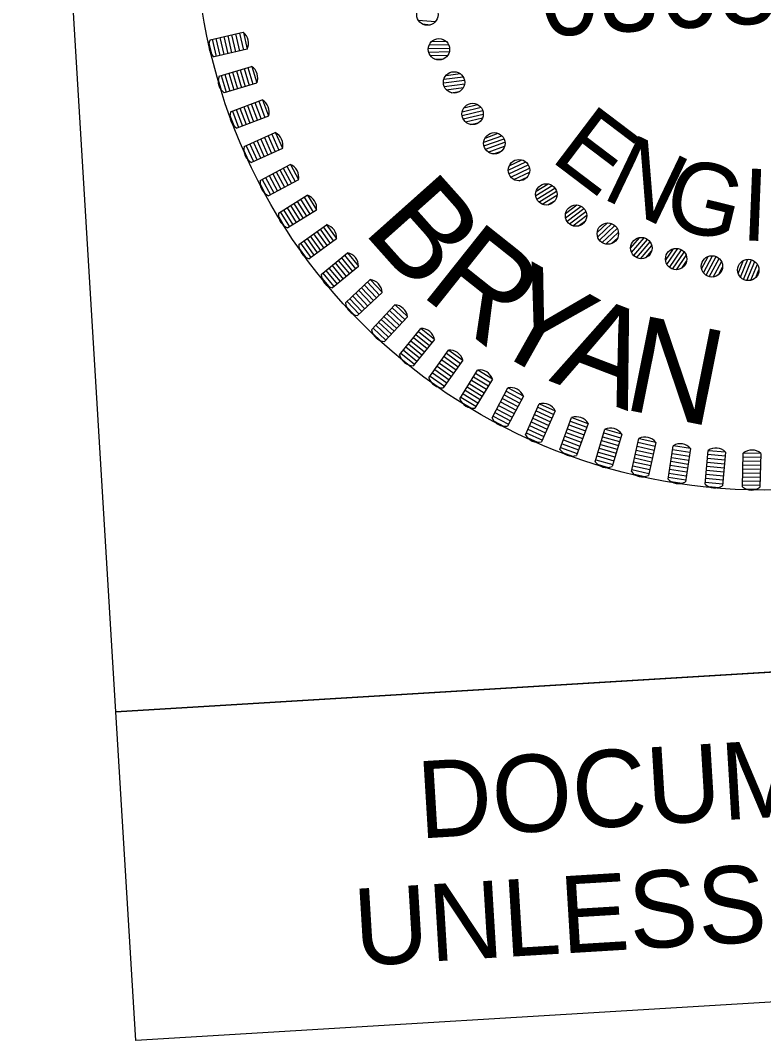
# Model space of a CAD drawing. Extents: x 2110128 to 2112690, y 669500 to 671339.
# Drawn here: x 2112240.6 to 2112293.6, y 670625.1 to 670697.9 of the extents above; entities that cross this region are included whole.
import ezdxf

# ---------------------------------------------------------------- set-up
doc = ezdxf.new("R2010")
doc.units = 0
for name, color, linetype in [('Exist Roads Curbs Text', 7, 'Continuous'), ('Exist Utilities Power Transformer Cogo Comment', 7, 'Continuous'), ('Exist Vegetation Woods Line Text', 7, 'Continuous')]:
    doc.layers.add(name, color=color, linetype=linetype)

msp = doc.modelspace()

# ---------------------------------------------------------------- linework, layer by layer
at = {"layer": 'Exist Roads Curbs Text'}
msp.add_lwpolyline([(2112240.598, 670760.885), (2112340.465, 670766.938), (2112347.271, 670654.644), (2112247.404, 670648.591)], close=True, dxfattribs=at)
at = {"layer": 'Exist Utilities Power Transformer Cogo Comment'}
for p, q in [((2112247.404, 670648.591), (2112447.075, 670660.693)), ((2112248.826, 670625.134), (2112247.404, 670648.591)), ((2112448.497, 670637.236), (2112248.826, 670625.134))]:
    msp.add_line(p, q, dxfattribs=at)
at = {"layer": 'Exist Vegetation Woods Line Text'}
for p, q in [((2112268.955, 670697.909), (2112270.191, 670697.812)), ((2112269.246, 670697.632), (2112269.86, 670697.583)), ((2112254.119, 670696.505), (2112256.474, 670697.047)), ((2112254.262, 670696.538), (2112254.543, 670695.32)), ((2112254.54, 670696.602), (2112254.821, 670695.384)), ((2112254.818, 670696.666), (2112255.099, 670695.448)), ((2112255.096, 670696.73), (2112255.377, 670695.512)), ((2112255.374, 670696.794), (2112255.655, 670695.576)), ((2112255.652, 670696.858), (2112255.933, 670695.64)), ((2112255.93, 670696.922), (2112256.211, 670695.704)), ((2112256.208, 670696.986), (2112256.489, 670695.768)), ((2112256.49, 670697.035), (2112256.763, 670695.847)), ((2112269.916, 670696.393), (2112270.921, 670696.419)), ((2112254.039, 670696.236), (2112254.21, 670695.494)), ((2112256.754, 670695.829), (2112254.399, 670695.287)), ((2112269.673, 670695.879), (2112271.191, 670695.918)), ((2112269.7, 670695.625), (2112271.176, 670695.663)), ((2112269.733, 670696.134), (2112271.117, 670696.17)), ((2112269.825, 670695.374), (2112271.065, 670695.406)), ((2112270.144, 670695.128), (2112270.759, 670695.144)), ((2112254.763, 670693.916), (2112257.077, 670694.612)), ((2112255.723, 670694.205), (2112256.083, 670693.008)), ((2112255.996, 670694.287), (2112256.357, 670693.09)), ((2112256.27, 670694.369), (2112256.63, 670693.172)), ((2112256.543, 670694.452), (2112256.903, 670693.254)), ((2112256.816, 670694.534), (2112257.176, 670693.337)), ((2112257.094, 670694.601), (2112257.445, 670693.434)), ((2112254.701, 670693.642), (2112254.92, 670692.913)), ((2112254.904, 670693.958), (2112255.264, 670692.761)), ((2112255.177, 670694.041), (2112255.537, 670692.844)), ((2112255.45, 670694.123), (2112255.81, 670692.926)), ((2112270.751, 670693.43), (2112272.257, 670693.627)), ((2112270.784, 670693.69), (2112272.157, 670693.871)), ((2112270.939, 670693.967), (2112271.936, 670694.098)), ((2112257.437, 670693.415), (2112255.123, 670692.719)), ((2112270.805, 670693.181), (2112272.269, 670693.373)), ((2112270.955, 670692.944), (2112272.185, 670693.106)), ((2112271.298, 670692.733), (2112271.908, 670692.813)), ((2112255.576, 670691.375), (2112257.84, 670692.223)), ((2112257.317, 670692.027), (2112257.756, 670690.856)), ((2112257.584, 670692.127), (2112258.023, 670690.956)), ((2112257.857, 670692.213), (2112258.284, 670691.071)), ((2112255.714, 670691.427), (2112256.153, 670690.256)), ((2112255.981, 670691.527), (2112256.42, 670690.356)), ((2112256.248, 670691.627), (2112256.687, 670690.456)), ((2112256.516, 670691.727), (2112256.954, 670690.556)), ((2112256.783, 670691.827), (2112257.221, 670690.656)), ((2112257.05, 670691.927), (2112257.488, 670690.756)), ((2112272.079, 670691.107), (2112273.556, 670691.461)), ((2112272.085, 670691.37), (2112273.432, 670691.692)), ((2112272.21, 670691.661), (2112273.188, 670691.895)), ((2112255.533, 670691.098), (2112255.8, 670690.385)), ((2112258.278, 670691.052), (2112256.015, 670690.204)), ((2112272.159, 670690.865), (2112273.595, 670691.209)), ((2112272.333, 670690.645), (2112273.539, 670690.934)), ((2112272.696, 670690.471), (2112273.294, 670690.614)), ((2112256.556, 670688.893), (2112258.758, 670689.889)), ((2112258.776, 670689.88), (2112259.278, 670688.769)), ((2112273.716, 670689.5), (2112274.663, 670689.836)), ((2112257.21, 670689.189), (2112257.725, 670688.05)), ((2112257.47, 670689.306), (2112257.985, 670688.167)), ((2112257.73, 670689.424), (2112258.245, 670688.285)), ((2112257.99, 670689.541), (2112258.505, 670688.402)), ((2112258.25, 670689.659), (2112258.765, 670688.52)), ((2112258.51, 670689.776), (2112259.025, 670688.637)), ((2112273.622, 670689.198), (2112274.927, 670689.659)), ((2112273.643, 670688.936), (2112275.075, 670689.442)), ((2112273.748, 670688.703), (2112275.14, 670689.196)), ((2112256.531, 670688.614), (2112256.845, 670687.92)), ((2112256.69, 670688.954), (2112257.205, 670687.815)), ((2112256.95, 670689.071), (2112257.465, 670687.932)), ((2112259.273, 670688.749), (2112257.071, 670687.754)), ((2112273.944, 670688.503), (2112275.113, 670688.917)), ((2112274.323, 670688.368), (2112274.903, 670688.573)), ((2112275.377, 670687.198), (2112276.626, 670687.794)), ((2112275.438, 670687.509), (2112276.346, 670687.941)), ((2112257.698, 670686.482), (2112259.829, 670687.62)), ((2112258.582, 670686.954), (2112259.171, 670685.852)), ((2112258.834, 670687.089), (2112259.423, 670685.986)), ((2112259.086, 670687.223), (2112259.675, 670686.12)), ((2112259.337, 670687.357), (2112259.926, 670686.255)), ((2112259.589, 670687.492), (2112260.178, 670686.389)), ((2112259.848, 670687.613), (2112260.422, 670686.537)), ((2112275.425, 670686.94), (2112276.796, 670687.593)), ((2112275.554, 670686.719), (2112276.887, 670687.355)), ((2112275.77, 670686.541), (2112276.889, 670687.074)), ((2112257.691, 670686.201), (2112258.05, 670685.529)), ((2112257.828, 670686.551), (2112258.417, 670685.448)), ((2112258.079, 670686.685), (2112258.668, 670685.583)), ((2112260.418, 670686.518), (2112258.287, 670685.379)), ((2112258.331, 670686.82), (2112258.92, 670685.717)), ((2112276.161, 670686.446), (2112276.716, 670686.711)), ((2112277.36, 670685.708), (2112278.217, 670686.233)), ((2112277.331, 670685.393), (2112278.512, 670686.116)), ((2112277.406, 670685.141), (2112278.702, 670685.934)), ((2112277.557, 670684.935), (2112278.816, 670685.707)), ((2112258.996, 670684.151), (2112261.048, 670685.428)), ((2112260.09, 670684.831), (2112260.75, 670683.77)), ((2112260.332, 670684.982), (2112260.993, 670683.921)), ((2112260.574, 670685.133), (2112261.235, 670684.072)), ((2112260.816, 670685.284), (2112261.477, 670684.223)), ((2112261.067, 670685.421), (2112261.711, 670684.386)), ((2112277.791, 670684.781), (2112278.848, 670685.428)), ((2112278.19, 670684.727), (2112278.714, 670685.048)), ((2112259.121, 670684.228), (2112259.782, 670683.167)), ((2112259.363, 670684.379), (2112260.024, 670683.318)), ((2112259.605, 670684.53), (2112260.266, 670683.469)), ((2112261.708, 670684.367), (2112259.657, 670683.089)), ((2112259.848, 670684.681), (2112260.508, 670683.619)), ((2112279.459, 670684.119), (2112280.257, 670684.73)), ((2112279.463, 670683.802), (2112280.562, 670684.644)), ((2112279.565, 670683.559), (2112280.77, 670684.484)), ((2112279.736, 670683.371), (2112280.908, 670684.269)), ((2112259.008, 670683.87), (2112259.411, 670683.224)), ((2112260.446, 670681.911), (2112262.409, 670683.321)), ((2112262.428, 670683.315), (2112263.139, 670682.325)), ((2112279.985, 670683.241), (2112280.969, 670683.995)), ((2112280.387, 670683.229), (2112280.875, 670683.604)), ((2112281.713, 670682.757), (2112282.443, 670683.449)), ((2112281.75, 670682.442), (2112282.755, 670683.395)), ((2112261.492, 670682.662), (2112262.221, 670681.647)), ((2112261.724, 670682.829), (2112262.453, 670681.813)), ((2112261.955, 670682.995), (2112262.685, 670681.98)), ((2112262.187, 670683.162), (2112262.916, 670682.146)), ((2112281.877, 670682.212), (2112282.979, 670683.257)), ((2112282.067, 670682.042), (2112283.138, 670683.058)), ((2112282.327, 670681.939), (2112283.227, 670682.792)), ((2112260.565, 670681.997), (2112261.295, 670680.981)), ((2112260.797, 670682.163), (2112261.526, 670681.148)), ((2112261.029, 670682.329), (2112261.758, 670681.314)), ((2112263.138, 670682.305), (2112261.175, 670680.895)), ((2112261.26, 670682.496), (2112261.99, 670681.481)), ((2112282.729, 670681.97), (2112283.175, 670682.393)), ((2112284.097, 670681.639), (2112284.75, 670682.403)), ((2112284.167, 670681.33), (2112285.067, 670682.382)), ((2112284.317, 670681.113), (2112285.303, 670682.268)), ((2112284.523, 670680.964), (2112285.483, 670682.087)), ((2112284.793, 670680.889), (2112285.599, 670681.832)), ((2112260.476, 670681.632), (2112260.921, 670681.013)), ((2112262.04, 670679.771), (2112263.906, 670681.308)), ((2112263.695, 670681.135), (2112264.49, 670680.17)), ((2112263.925, 670681.304), (2112264.7, 670680.363)), ((2112285.189, 670680.962), (2112285.589, 670681.429)), ((2112286.585, 670680.776), (2112287.154, 670681.604)), ((2112286.687, 670680.475), (2112287.471, 670681.616)), ((2112286.858, 670680.276), (2112287.719, 670681.527)), ((2112287.079, 670680.149), (2112287.916, 670681.366)), ((2112287.356, 670680.103), (2112288.058, 670681.125)), ((2112289.282, 670679.889), (2112289.943, 670681.106)), ((2112262.815, 670680.409), (2112263.609, 670679.444)), ((2112263.035, 670680.591), (2112263.83, 670679.626)), ((2112263.255, 670680.772), (2112264.05, 670679.807)), ((2112263.475, 670680.953), (2112264.27, 670679.988)), ((2112287.742, 670680.216), (2112288.091, 670680.723)), ((2112289.149, 670680.177), (2112289.629, 670681.06)), ((2112289.473, 670679.709), (2112290.198, 670681.043)), ((2112289.706, 670679.606), (2112290.411, 670680.904)), ((2112289.986, 670679.589), (2112290.578, 670680.678)), ((2112291.762, 670679.85), (2112292.147, 670680.779)), ((2112291.924, 670679.578), (2112292.454, 670680.857)), ((2112292.133, 670679.418), (2112292.715, 670680.821)), ((2112292.376, 670679.34), (2112292.941, 670680.705)), ((2112292.656, 670679.352), (2112293.131, 670680.498)), ((2112262.154, 670679.865), (2112262.949, 670678.9)), ((2112262.374, 670680.046), (2112263.169, 670679.082)), ((2112262.594, 670680.228), (2112263.389, 670679.263)), ((2112264.701, 670680.343), (2112262.835, 670678.807)), ((2112290.358, 670679.742), (2112290.652, 670680.283)), ((2112293.01, 670679.544), (2112293.246, 670680.112)), ((2112262.089, 670679.495), (2112262.573, 670678.907)), ((2112263.773, 670677.742), (2112265.532, 670679.399)), ((2112265.126, 670679.016), (2112265.983, 670678.106)), ((2112265.334, 670679.212), (2112266.191, 670678.302)), ((2112265.552, 670679.396), (2112266.388, 670678.509)), ((2112264.295, 670678.234), (2112265.152, 670677.324)), ((2112264.503, 670678.43), (2112265.36, 670677.52)), ((2112266.389, 670678.489), (2112264.63, 670676.832)), ((2112264.711, 670678.625), (2112265.568, 670677.715)), ((2112264.919, 670678.821), (2112265.775, 670677.911)), ((2112263.84, 670677.47), (2112264.362, 670676.915)), ((2112263.88, 670677.843), (2112264.737, 670676.933)), ((2112264.088, 670678.039), (2112264.945, 670677.129)), ((2112265.636, 670675.832), (2112267.282, 670677.601)), ((2112267.302, 670677.6), (2112268.194, 670676.769)), ((2112266.513, 670676.775), (2112267.428, 670675.924)), ((2112268.197, 670676.75), (2112266.551, 670674.98)), ((2112266.708, 670676.984), (2112267.623, 670676.132)), ((2112266.902, 670677.193), (2112267.817, 670676.341)), ((2112267.096, 670677.402), (2112268.011, 670676.55)), ((2112265.93, 670676.149), (2112266.845, 670675.297)), ((2112266.125, 670676.357), (2112267.04, 670675.506)), ((2112266.319, 670676.566), (2112267.234, 670675.715)), ((2112265.72, 670675.565), (2112266.278, 670675.046)), ((2112265.736, 670675.94), (2112266.651, 670675.088)), ((2112267.621, 670674.049), (2112269.146, 670675.923)), ((2112268.794, 670675.491), (2112269.764, 670674.701)), ((2112268.974, 670675.712), (2112269.944, 670674.923)), ((2112269.166, 670675.923), (2112270.112, 670675.154)), ((2112268.074, 670674.606), (2112269.043, 670673.816)), ((2112268.254, 670674.827), (2112269.223, 670674.038)), ((2112268.434, 670675.048), (2112269.403, 670674.259)), ((2112270.116, 670675.134), (2112268.59, 670673.26)), ((2112268.614, 670675.269), (2112269.583, 670674.48)), ((2112267.714, 670674.163), (2112268.683, 670673.374)), ((2112267.894, 670674.384), (2112268.863, 670673.595)), ((2112269.719, 670672.401), (2112271.118, 670674.372)), ((2112270.795, 670673.917), (2112271.814, 670673.194)), ((2112270.96, 670674.15), (2112271.979, 670673.426)), ((2112271.138, 670674.373), (2112272.132, 670673.668)), ((2112267.723, 670673.788), (2112268.313, 670673.307)), ((2112270.299, 670673.219), (2112271.319, 670672.496)), ((2112270.465, 670673.452), (2112271.484, 670672.728)), ((2112270.63, 670673.684), (2112271.649, 670672.961)), ((2112272.137, 670673.649), (2112270.739, 670671.678)), ((2112269.804, 670672.521), (2112270.824, 670671.798)), ((2112269.969, 670672.754), (2112270.989, 670672.03)), ((2112270.134, 670672.987), (2112271.154, 670672.263)), ((2112271.922, 670670.896), (2112273.187, 670672.955)), ((2112272.895, 670672.479), (2112273.96, 670671.825)), ((2112273.044, 670672.722), (2112274.109, 670672.068)), ((2112273.207, 670672.957), (2112274.245, 670672.319)), ((2112269.838, 670672.147), (2112270.459, 670671.707)), ((2112272.447, 670671.75), (2112273.512, 670671.096)), ((2112272.596, 670671.993), (2112273.661, 670671.339)), ((2112272.746, 670672.236), (2112273.811, 670671.582)), ((2112274.252, 670672.3), (2112272.987, 670670.241)), ((2112274.219, 670669.539), (2112275.346, 670671.677)), ((2112275.365, 670671.681), (2112276.444, 670671.113)), ((2112271.999, 670671.021), (2112273.064, 670670.367)), ((2112272.148, 670671.264), (2112273.213, 670670.61)), ((2112272.298, 670671.507), (2112273.363, 670670.853)), ((2112274.953, 670670.931), (2112276.059, 670670.348)), ((2112275.086, 670671.183), (2112276.192, 670670.601)), ((2112275.219, 670671.436), (2112276.325, 670670.853)), ((2112276.452, 670671.094), (2112275.325, 670668.956)), ((2112272.058, 670670.65), (2112272.706, 670670.251)), ((2112274.687, 670670.426), (2112275.793, 670669.844)), ((2112274.82, 670670.679), (2112275.926, 670670.096)), ((2112276.601, 670668.337), (2112277.584, 670670.545)), ((2112277.473, 670670.296), (2112278.615, 670669.787)), ((2112277.603, 670670.55), (2112278.717, 670670.054)), ((2112274.288, 670669.669), (2112275.394, 670669.086)), ((2112274.421, 670669.922), (2112275.527, 670669.339)), ((2112274.554, 670670.174), (2112275.66, 670669.591)), ((2112277.125, 670669.514), (2112278.267, 670669.006)), ((2112277.241, 670669.775), (2112278.383, 670669.266)), ((2112277.357, 670670.035), (2112278.499, 670669.527)), ((2112278.726, 670670.037), (2112277.743, 670667.829)), ((2112279.058, 670667.295), (2112279.892, 670669.563)), ((2112279.911, 670669.57), (2112281.055, 670669.149)), ((2112274.371, 670669.303), (2112275.045, 670668.948)), ((2112276.777, 670668.732), (2112277.919, 670668.224)), ((2112276.893, 670668.993), (2112278.035, 670668.484)), ((2112277.009, 670669.253), (2112278.151, 670668.745)), ((2112279.601, 670668.772), (2112280.774, 670668.34)), ((2112279.7, 670669.04), (2112280.873, 670668.608)), ((2112279.798, 670669.307), (2112280.971, 670668.876)), ((2112281.065, 670669.132), (2112280.231, 670666.863)), ((2112281.578, 670666.418), (2112282.26, 670668.736)), ((2112282.279, 670668.744), (2112283.448, 670668.399)), ((2112276.661, 670668.471), (2112277.803, 670667.963)), ((2112276.768, 670668.112), (2112277.464, 670667.802)), ((2112279.404, 670668.236), (2112280.577, 670667.805)), ((2112279.503, 670668.504), (2112280.676, 670668.072)), ((2112282.103, 670668.201), (2112283.302, 670667.848)), ((2112282.183, 670668.475), (2112283.382, 670668.121)), ((2112283.46, 670668.383), (2112282.777, 670666.065)), ((2112284.15, 670665.709), (2112284.678, 670668.067)), ((2112284.696, 670668.076), (2112285.885, 670667.81)), ((2112279.109, 670667.433), (2112280.282, 670667.002)), ((2112279.207, 670667.701), (2112280.38, 670667.269)), ((2112279.306, 670667.969), (2112280.479, 670667.537)), ((2112281.861, 670667.38), (2112283.06, 670667.027)), ((2112281.942, 670667.654), (2112283.141, 670667.3)), ((2112282.022, 670667.927), (2112283.221, 670667.574)), ((2112284.556, 670667.523), (2112285.776, 670667.25)), ((2112284.618, 670667.801), (2112285.838, 670667.528)), ((2112285.898, 670667.794), (2112285.37, 670665.436)), ((2112286.763, 670665.172), (2112287.134, 670667.56)), ((2112287.093, 670667.291), (2112288.328, 670667.099)), ((2112287.152, 670667.57), (2112288.356, 670667.383)), ((2112288.37, 670667.368), (2112287.999, 670664.98)), ((2112279.239, 670667.081), (2112279.954, 670666.818)), ((2112281.619, 670666.559), (2112282.818, 670666.206)), ((2112281.7, 670666.833), (2112282.899, 670666.48)), ((2112281.78, 670667.106), (2112282.979, 670666.753)), ((2112284.369, 670666.688), (2112285.589, 670666.415)), ((2112284.431, 670666.966), (2112285.651, 670666.693)), ((2112284.494, 670667.245), (2112285.714, 670666.971)), ((2112287.005, 670666.727), (2112288.24, 670666.535)), ((2112287.049, 670667.009), (2112288.284, 670666.817)), ((2112289.407, 670664.809), (2112289.619, 670667.216)), ((2112289.57, 670666.66), (2112290.815, 670666.55)), ((2112289.595, 670666.944), (2112290.84, 670666.834)), ((2112289.636, 670667.227), (2112290.85, 670667.12)), ((2112290.864, 670667.106), (2112290.652, 670664.699)), ((2112292.068, 670664.621), (2112292.121, 670667.037)), ((2112292.115, 670666.764), (2112293.365, 670666.737)), ((2112292.137, 670667.049), (2112293.356, 670667.022)), ((2112293.371, 670667.01), (2112293.318, 670664.593)), ((2112281.773, 670666.216), (2112282.503, 670666.001)), ((2112284.182, 670665.853), (2112285.402, 670665.58)), ((2112284.244, 670666.131), (2112285.464, 670665.858)), ((2112284.307, 670666.41), (2112285.527, 670666.136)), ((2112286.874, 670665.881), (2112288.109, 670665.689)), ((2112286.917, 670666.163), (2112288.153, 670665.971)), ((2112286.961, 670666.445), (2112288.196, 670666.253)), ((2112289.52, 670666.092), (2112290.765, 670665.982)), ((2112289.545, 670666.376), (2112290.79, 670666.266)), ((2112292.096, 670665.909), (2112293.346, 670665.881)), ((2112292.103, 670666.194), (2112293.352, 670666.167)), ((2112292.109, 670666.479), (2112293.359, 670666.452)), ((2112284.358, 670665.521), (2112285.101, 670665.355)), ((2112286.786, 670665.317), (2112288.021, 670665.125)), ((2112286.83, 670665.599), (2112288.065, 670665.407)), ((2112289.445, 670665.239), (2112290.69, 670665.13)), ((2112289.47, 670665.524), (2112290.715, 670665.414)), ((2112289.495, 670665.808), (2112290.74, 670665.698)), ((2112292.084, 670665.338), (2112293.334, 670665.311)), ((2112292.09, 670665.624), (2112293.34, 670665.596)), ((2112286.984, 670664.998), (2112287.736, 670664.881)), ((2112289.42, 670664.955), (2112290.665, 670664.845)), ((2112289.638, 670664.65), (2112290.396, 670664.583)), ((2112292.071, 670664.768), (2112293.321, 670664.741)), ((2112292.078, 670665.053), (2112293.327, 670665.026)), ((2112292.309, 670664.477), (2112293.071, 670664.461))]:
    msp.add_line(p, q, dxfattribs=at)
for centre, radius in [((2112293.63, 670704.945), 40.556), ((2112269.608, 670698.302), 0.762), ((2112270.433, 670695.834), 0.762), ((2112271.512, 670693.464), 0.762), ((2112272.833, 670691.221), 0.762), ((2112274.381, 670689.128), 0.762), ((2112276.139, 670687.208), 0.762), ((2112278.088, 670685.482), 0.762), ((2112280.207, 670683.97), 0.762), ((2112282.472, 670682.687), 0.762), ((2112284.859, 670681.649), 0.762), ((2112287.342, 670680.865), 0.762), ((2112289.893, 670680.345), 0.762), ((2112292.484, 670680.095), 0.762)]:
    msp.add_circle(centre, radius, dxfattribs=at)
for centre, radius, start, end in [((2112255.06, 670696.08), 1.032, 155.68573, 230.2267), ((2112255.875, 670696.268), 0.983, 333.45947, 52.45296), ((2112256.531, 670693.795), 0.983, 337.24894, 56.24243), ((2112255.729, 670693.554), 1.032, 159.4752, 234.01617), ((2112257.349, 670691.371), 0.983, 341.03842, 60.03191), ((2112256.565, 670691.078), 1.032, 163.26468, 237.80565), ((2112258.325, 670689.007), 0.983, 344.82789, 63.82138), ((2112257.562, 670688.662), 1.032, 167.05415, 241.59512), ((2112259.455, 670686.712), 0.983, 348.61736, 67.61086), ((2112258.717, 670686.317), 1.032, 170.84363, 245.38459), ((2112260.734, 670684.496), 0.983, 352.40684, 71.40033), ((2112260.024, 670684.054), 1.032, 174.6331, 249.17407), ((2112262.157, 670682.371), 0.983, 356.19631, 75.1898), ((2112261.478, 670681.882), 1.032, 178.42257, 252.96354), ((2112263.718, 670680.344), 0.983, 359.98578, 78.97928), ((2112263.072, 670679.811), 1.032, 182.21205, 256.75302), ((2112265.409, 670678.424), 0.983, 3.77526, 82.76875), ((2112264.799, 670677.85), 1.032, 186.00152, 260.54249), ((2112267.223, 670676.62), 0.983, 7.56473, 86.55822), ((2112266.653, 670676.008), 1.032, 189.79099, 264.33196), ((2112269.152, 670674.941), 0.983, 11.35421, 90.3477), ((2112268.624, 670674.291), 1.032, 193.58047, 268.12144), ((2112271.189, 670673.392), 0.983, 15.14368, 94.13717), ((2112270.704, 670672.709), 1.032, 197.36994, 271.91091), ((2112273.323, 670671.981), 0.983, 18.93315, 97.92665), ((2112275.545, 670670.715), 0.983, 22.72263, 101.71612), ((2112272.884, 670671.268), 1.032, 201.15942, 275.70038), ((2112277.847, 670669.598), 0.983, 26.5121, 105.50559), ((2112275.155, 670669.974), 1.032, 204.94889, 279.48986), ((2112280.217, 670668.636), 0.983, 30.30157, 109.29507), ((2112282.646, 670667.832), 0.983, 34.09105, 113.08454), ((2112277.506, 670668.833), 1.032, 208.73836, 283.27933), ((2112285.122, 670667.191), 0.983, 37.88052, 116.87401), ((2112279.928, 670667.85), 1.032, 212.52784, 287.0688), ((2112287.636, 670666.715), 0.983, 41.67, 120.66349), ((2112290.175, 670666.406), 0.983, 45.45947, 124.45296), ((2112292.729, 670666.265), 0.983, 49.24894, 128.24243), ((2112282.409, 670667.029), 1.032, 216.31731, 290.85828), ((2112284.939, 670666.374), 1.032, 220.10678, 294.64775), ((2112287.507, 670665.888), 1.032, 223.89626, 298.43723), ((2112290.101, 670665.572), 1.032, 227.68573, 302.2267), ((2112292.711, 670665.428), 1.032, 231.4752, 306.01617)]:
    msp.add_arc(centre, radius, start, end, dxfattribs=at)

# ---------------------------------------------------------------- texts
at = {"layer": 'Exist Utilities Power Transformer Cogo Comment'}
for s, p in [('DOCUMENT NOT CONSIDERED FINAL', (2112269.062, 670639.54)), ('UNLESS ALL SIGNATURES COMPLETED', (2112264.533, 670630.449))]:
    msp.add_text(s, height=5.5, rotation=3.46824, dxfattribs=at).set_placement(p)
at = {"layer": 'Exist Vegetation Woods Line Text'}
for s, height, rotation, p in [('036853', 5.7051, 3.48253, (2112277.746, 670696.719)), ('E', 5.135, 322.83737, (2112278.283, 670687.954)), ('N', 5.135, 334.45027, (2112281.933, 670685.263)), ('G', 5.135, 346.06318, (2112286.222, 670683.3)), ('I', 5.135, 357.67608, (2112291.92, 670682.214)), ('B', 6.846, 311.71927, (2112264.919, 670682.886)), ('R', 6.846, 321.51736, (2112268.988, 670678.412)), ('Y', 6.846, 330.63849, (2112273.505, 670674.85)), ('A', 6.846, 339.0042, (2112278.218, 670672.203)), ('N', 6.846, 348.64286, (2112283.405, 670670.196))]:
    msp.add_text(s, height=height, rotation=rotation, dxfattribs=at).set_placement(p)

doc.saveas('drawing.dxf')
